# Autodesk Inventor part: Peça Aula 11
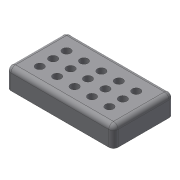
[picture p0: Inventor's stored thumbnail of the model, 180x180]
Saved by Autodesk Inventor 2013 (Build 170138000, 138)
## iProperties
Created: 2012-12
Part Number: Peça Aula 11
Material: Genérico
Document SubType Name: Modeling
Designer: Daniel Severino
Density: 1 g/cm^3
Author: Daniel Severino
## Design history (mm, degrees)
sketch "Esboço1"
  geometry: L1 (0, 0)-(0, 45); L2 (0, 45)-(80, 45); L3 (80, 45)-(80, 0); L4 (80, 0)-(0, 0)
  constraints: 8 end point, 2 vertical, 1 horizontal
  dimensions: "d0" = 45 distance of L1.start L1.end; "d1" = 80 distance of L1.end L2.end
extrude "Ext Base/Furo" new body sketch "Esboço1" distance "d5" = 15; taper "d6" = 0 deg
fillet "Arredondamento1" dims "d26" = 3.5
sketch "Esboço6"
  geometry: L1 (3.5, 41.5)-(76.5, 41.5) reference; L2 (3.5, 3.5)-(3.5, 41.5) reference; C1 r 3 at (13.5, 31.5); 1 further point
  constraints: 1 centre point
  dimensions: "d44" = 6 diameter of C1; "d46" = 10 distance from line of L2 C1.centre; "d47" = 10 distance from line of C1.centre L1
extrude "Extrusão6" cut sketch "Esboço6" stored distance "d48" = 10; taper "d49" = 0 deg
pattern_linear "Padrão retangular1" dims "d52" = 13
node "Sólido1"
